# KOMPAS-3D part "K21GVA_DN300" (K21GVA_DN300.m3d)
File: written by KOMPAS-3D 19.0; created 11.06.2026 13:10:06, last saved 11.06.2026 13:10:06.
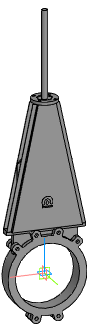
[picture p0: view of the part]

Document properties: Автор: Энергия; Полное имя файла: Z:\3.Личные\kachalov\001_3d для проектировщиков\2.5 Тип_K21GVA. Задвижка\_stp\_stp_K21GVA_DN50-DN1000_с фланцем\K21GVA_DN300.m3d

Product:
- Part/product: K21GVA_DN300

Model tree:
1. Операция без истории:1  (labels: K21GVA_DN300)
